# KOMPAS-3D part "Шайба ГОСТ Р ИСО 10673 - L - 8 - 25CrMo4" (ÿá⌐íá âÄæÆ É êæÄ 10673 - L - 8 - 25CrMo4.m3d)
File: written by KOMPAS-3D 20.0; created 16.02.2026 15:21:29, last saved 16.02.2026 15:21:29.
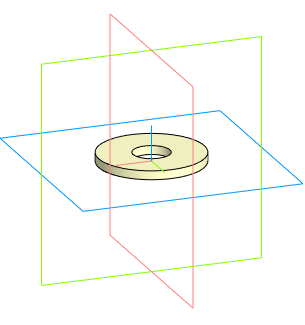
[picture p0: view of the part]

Document properties: Автор: admin; Полное имя файла: P:\INSTART\Технический отдел\ОР\Прочие задачи\КД на номенклатурный ряд\КД на типоразмеры дросселей\Сетевые дроссели ISF\ISF-4\Тип 1\ISF-132_256-4\0723\Новая папка\Шайба ГОСТ Р ИСО 10673 - L - 8 - 25CrMo4.m3d

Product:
- Part/product: Шайба ГОСТ Р ИСО 10673 - L - 8 - 25CrMo4

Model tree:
1. Операция без истории:1  (labels: Шайба ГОСТ Р ИСО 10673 - L - 8 - 25CrMo4)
